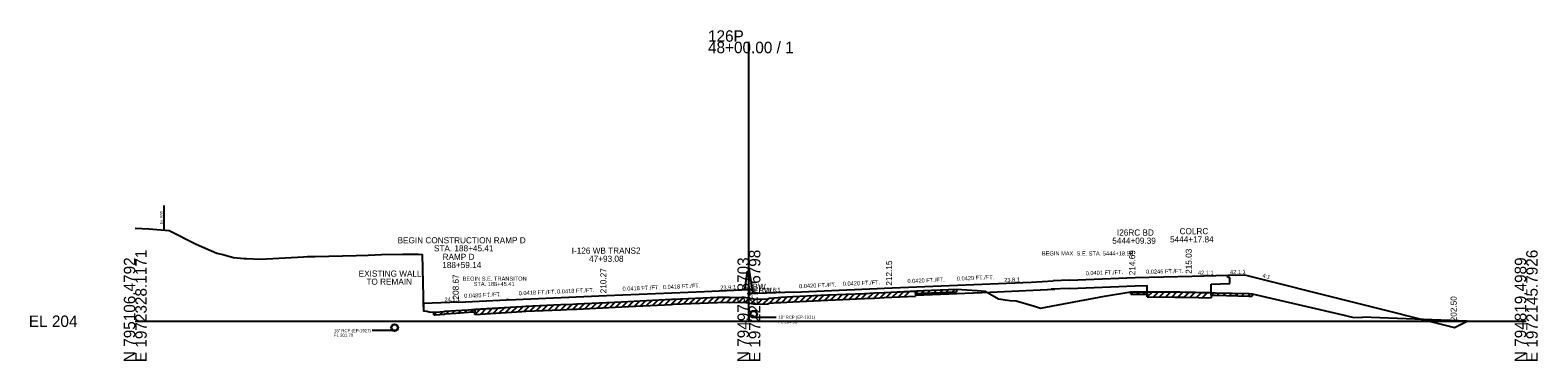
# Model space of a CAD drawing. Extents: x -161 to 1970889, y -4362 to 797231.
# Drawn here: x 1974.3 to 2342.8, y 490.3 to 571.2 of the extents above; entities that cross this region are included whole.
import ezdxf

# ---------------------------------------------------------------- set-up
doc = ezdxf.new("R2010")
doc.units = 0
for name, color, linetype in [('RD_GPK_XS_Cell', 7, 'Continuous'), ('RD_XS_Base', 7, 'Continuous'), ('RD_XS_EarthShd', 7, 'Continuous'), ('RD_XS_ExGround', 7, 'Continuous'), ('RD_XS_ExPaveRet', 7, 'Continuous'), ('RD_XS_ExRW', 7, 'Continuous'), ('RD_XS_MedBWall', 7, 'Continuous'), ('RD_XS_Misc_Line', 7, 'Continuous'), ('RD_XS_Pave', 7, 'Continuous'), ('RD_XS_PaveOvlay', 7, 'Continuous'), ('RD_XS_PaveShd', 7, 'Continuous'), ('RD_XS_Pipe', 7, 'Continuous'), ('RD_XS_TieSlope', 7, 'Continuous'), ('RD_XS_TX_Elev_EX', 7, 'Continuous'), ('RD_XS_TX_Elev_PR', 7, 'Continuous'), ('RD_XS_TX_Misc', 7, 'Continuous'), ('RD_XS_TX_MkPT', 7, 'Continuous'), ('RD_XS_TX_Notes', 7, 'Continuous'), ('RD_XS_TX_Profile', 7, 'Continuous'), ('RD_XS_TX_ShdSlope', 7, 'Continuous'), ('RD_XS_TX_Slope', 7, 'Continuous'), ('RD_XS_TX_Station', 7, 'Continuous')]:
    doc.layers.add(name, color=color, linetype=linetype)

msp = doc.modelspace()

# ---------------------------------------------------------------- linework, layer by layer
at = {"layer": 'RD_GPK_XS_Cell'}
for p, q in [((2150, 500), (2150, 568.35)), ((2000, 500), (2150, 500)), ((2150, 500), (2340, 500))]:
    msp.add_line(p, q, dxfattribs=at)
at = {"layer": 'RD_XS_Base'}
for p, q in [((2228.36, 508.01), (2244.42, 508.65)), ((2244.42, 508.65), (2247.37, 508.72)), ((2262.95, 509.1), (2267.58, 509.21)), ((2267.08, 510.68), (2267.08, 511.24)), ((2267.58, 510.69), (2267.08, 510.68)), ((2267.58, 509.21), (2267.58, 510.69)), ((2190.72, 506.35), (2209, 507.12)), ((2209, 507.12), (2219.5, 507.56)), ((2219.5, 507.56), (2224.75, 507.86)), ((2228.36, 508.01), (2223.84, 507.83)), ((2228.36, 508), (2223.84, 507.82))]:
    msp.add_line(p, q, dxfattribs=at)
at = {"layer": 'RD_XS_EarthShd'}
msp.add_line((2267.08, 511.24), (2271.11, 511.34), dxfattribs=at)
at = {"layer": 'RD_XS_ExGround'}
msp.add_line((2325.53, 500.03), (2300, 501), dxfattribs=at)
msp.add_lwpolyline([(2000, 522.78), (2003.3, 522.58), (2008.25, 522.19), (2014.85, 518.85), (2019.97, 516.66), (2021.39, 516.29), (2024.04, 515.61), (2026.58, 515.36), (2027.11, 515.34), (2030.62, 515.18), (2041.15, 515.78), (2042.08, 515.83), (2043.57, 515.87), (2043.99, 515.87), (2053.97, 516.1), (2056.89, 516.19), (2060.17, 516.3), (2065.43, 516.37), (2069.26, 516.36), (2070.12, 516.35), (2070.44, 502.56), (2071.29, 502.44), (2071.85, 502.33), (2072.88, 502.23), (2073.29, 502.19), (2075.52, 502.35), (2075.69, 502.44), (2078.36, 502.62), (2081.45, 502.82), (2094.53, 503.61), (2095.44, 503.67), (2104, 504.06), (2106.99, 504.2), (2107.92, 504.24), (2118.87, 504.76), (2131.08, 505.38), (2131.48, 505.4), (2142.35, 505.87), (2145.14, 505.88), (2145.34, 505.83), (2148.73, 505.92), (2150.22, 505.64), (2151.52, 505.41), (2154.65, 505.51), (2154.96, 505.67), (2157.16, 505.82), (2157.83, 505.86), (2160.72, 506.01), (2169.28, 506.42), (2178.22, 506.81), (2180.8, 506.92), (2183.07, 507.03), (2192.71, 507.49), (2198.75, 507.76), (2200.72, 507.85), (2205.83, 507.52), (2207.74, 507.38), (2208.89, 506.69), (2211.03, 505.48), (2213.8, 505.08), (2215.34, 504.95), (2219.82, 503.65), (2221.25, 503.17), (2226.88, 504.24), (2236.94, 506.1), (2243.33, 507.21), (2245.08, 507.22), (2247.12, 507.21), (2254.1, 507.17), (2255.31, 507.16), (2256.72, 507.13), (2263.93, 506.98), (2272.3, 506.74), (2273.04, 506.72), (2294.14, 501.81), (2297.84, 500.93), (2300, 501)], dxfattribs=at)
at = {"layer": 'RD_XS_ExPaveRet'}
for p, q in [((2160.72, 504.76), (2169.28, 505.17)), ((2169.28, 505.17), (2178.22, 505.56)), ((2178.22, 505.56), (2180.8, 505.67)), ((2180.8, 505.67), (2183.07, 505.78)), ((2183.07, 505.78), (2190.72, 506.14)), ((2190.72, 507.39), (2190.72, 506.14)), ((2190.72, 506.77), (2190.72, 507.39)), ((2190.72, 506.77), (2192.71, 506.86)), ((2192.71, 506.86), (2198.75, 507.14)), ((2198.75, 507.14), (2200.72, 507.22)), ((2200.72, 507.85), (2200.72, 507.22)), ((2243.33, 506.59), (2243.33, 507.21)), ((2243.33, 506.59), (2245.08, 506.59)), ((2245.08, 506.59), (2247.12, 506.58)), ((2247.12, 506.58), (2247.37, 506.58)), ((2247.37, 505.96), (2247.37, 507.21)), ((2247.37, 507.21), (2247.37, 506.58)), ((2247.37, 505.96), (2254.1, 505.92)), ((2254.1, 505.92), (2255.31, 505.91)), ((2255.31, 505.91), (2256.72, 505.88)), ((2256.72, 505.88), (2262.95, 505.75)), ((2262.95, 507), (2262.95, 505.75)), ((2262.95, 506.38), (2262.95, 507)), ((2262.95, 506.38), (2263.93, 506.36)), ((2263.93, 506.36), (2272.3, 506.11)), ((2272.3, 506.11), (2273.04, 506.09)), ((2273.04, 506.72), (2273.04, 506.09)), ((2072.97, 501.6), (2072.97, 502.23)), ((2072.97, 501.6), (2073.29, 501.57)), ((2073.29, 501.57), (2075.52, 501.73)), ((2075.52, 501.73), (2075.69, 501.81)), ((2075.69, 501.81), (2078.36, 501.99)), ((2078.36, 501.99), (2081.45, 502.19)), ((2081.45, 502.19), (2082.97, 502.28)), ((2082.97, 501.66), (2082.97, 502.91)), ((2082.97, 502.91), (2082.97, 502.28)), ((2082.97, 501.66), (2094.53, 502.36)), ((2094.53, 502.36), (2095.44, 502.42)), ((2095.44, 502.42), (2104, 502.81)), ((2104, 502.81), (2106.99, 502.95)), ((2106.99, 502.95), (2107.92, 502.99)), ((2107.92, 502.99), (2118.87, 503.51)), ((2118.87, 503.51), (2131.08, 504.13)), ((2131.08, 504.13), (2131.48, 504.15)), ((2131.48, 504.15), (2142.35, 504.62)), ((2142.35, 504.62), (2145.14, 504.63)), ((2145.14, 504.63), (2145.34, 504.58)), ((2145.34, 504.58), (2148.73, 504.67)), ((2148.73, 504.67), (2150.22, 504.39)), ((2150.22, 504.39), (2151.52, 504.16)), ((2151.52, 504.16), (2154.65, 504.26)), ((2154.65, 504.26), (2154.96, 504.42)), ((2154.96, 504.42), (2157.16, 504.57)), ((2157.16, 504.57), (2157.83, 504.61)), ((2157.83, 504.61), (2160.72, 504.76))]:
    msp.add_line(p, q, dxfattribs=at)
at = {"layer": 'RD_XS_ExRW'}
msp.add_line((2006.95, 528.29), (2006.95, 522.29), dxfattribs=at)
at = {"layer": 'RD_XS_MedBWall'}
for p, q in [((2149, 507.68), (2149.67, 512.22)), ((2150.18, 512.22), (2149.67, 512.22)), ((2151, 506.72), (2150.18, 512.22))]:
    msp.add_line(p, q, dxfattribs=at)
at = {"layer": 'RD_XS_Misc_Line'}
for p, q in [((2120.5, 503.6), (2121.82, 504.91)), ((2122, 503.67), (2123.32, 504.99)), ((2123.5, 503.75), (2124.82, 505.06)), ((2125, 503.82), (2126.32, 505.14)), ((2126.5, 503.9), (2127.82, 505.22)), ((2128.01, 503.98), (2129.32, 505.29)), ((2129.51, 504.05), (2130.82, 505.37)), ((2131.01, 504.13), (2132.31, 505.43)), ((2132.51, 504.19), (2133.82, 505.5)), ((2134.01, 504.26), (2135.32, 505.56)), ((2135.51, 504.32), (2136.82, 505.63)), ((2137.01, 504.39), (2138.32, 505.69)), ((2138.51, 504.45), (2139.82, 505.76)), ((2140.01, 504.52), (2141.32, 505.82)), ((2141.51, 504.58), (2142.8, 505.87)), ((2143.02, 504.62), (2144.27, 505.87)), ((2144.52, 504.62), (2145.73, 505.84)), ((2146.02, 504.6), (2147.3, 505.88)), ((2147.52, 504.63), (2148.79, 505.91)), ((2149.02, 504.61), (2150.08, 505.67)), ((2150.52, 504.34), (2151.59, 505.41)), ((2152.02, 504.17), (2153.32, 505.47)), ((2153.52, 504.23), (2154.97, 505.67)), ((2155.02, 504.42), (2156.37, 505.77)), ((2156.52, 504.53), (2157.86, 505.86)), ((2158.03, 504.62), (2159.34, 505.94)), ((2159.53, 504.7), (2160.84, 506.01)), ((2161.03, 504.77), (2162.34, 506.09)), ((2162.53, 504.85), (2163.84, 506.16)), ((2164.03, 504.92), (2165.34, 506.23)), ((2165.53, 504.99), (2166.84, 506.3)), ((2167.03, 505.06), (2168.35, 506.38)), ((2168.53, 505.14), (2169.84, 506.45)), ((2170.03, 505.2), (2171.34, 506.51)), ((2171.53, 505.27), (2172.84, 506.58)), ((2173.04, 505.34), (2174.34, 506.64)), ((2174.54, 505.4), (2175.84, 506.71)), ((2176.04, 505.47), (2177.35, 506.77)), ((2177.54, 505.53), (2178.85, 506.84)), ((2179.04, 505.6), (2180.35, 506.9)), ((2180.54, 505.66), (2181.85, 506.97)), ((2182.04, 505.73), (2183.35, 507.04)), ((2183.54, 505.8), (2184.86, 507.11)), ((2185.04, 505.87), (2186.36, 507.19)), ((2186.54, 505.94), (2187.86, 507.26)), ((2188.05, 506.02), (2189.36, 507.33)), ((2190.72, 506.77), (2191.38, 507.43)), ((2192.22, 506.84), (2192.88, 507.5)), ((2193.73, 506.91), (2194.38, 507.56)), ((2195.23, 506.98), (2195.88, 507.63)), ((2196.73, 507.04), (2197.38, 507.7)), ((2198.23, 507.11), (2198.88, 507.77)), ((2199.73, 507.18), (2200.38, 507.83)), ((2243.33, 506.59), (2243.96, 507.21)), ((2244.83, 506.59), (2245.45, 507.22)), ((2246.33, 506.59), (2246.95, 507.21)), ((2247.37, 505.96), (2248.61, 507.2)), ((2248.87, 505.95), (2250.11, 507.19)), ((2250.37, 505.94), (2251.61, 507.18)), ((2251.87, 505.93), (2253.12, 507.18)), ((2253.37, 505.92), (2254.61, 507.17)), ((2254.87, 505.91), (2256.1, 507.14)), ((2256.37, 505.89), (2257.6, 507.11)), ((2257.87, 505.86), (2259.1, 507.08)), ((2259.38, 505.83), (2260.6, 507.05)), ((2260.88, 505.8), (2262.1, 507.02)), ((2262.95, 506.38), (2263.56, 506.99)), ((2264.45, 506.34), (2265.06, 506.95)), ((2265.95, 506.3), (2266.56, 506.91)), ((2267.45, 506.26), (2268.06, 506.86)), ((2268.95, 506.21), (2269.56, 506.82)), ((2270.45, 506.17), (2271.06, 506.77)), ((2271.96, 506.12), (2272.56, 506.73)), ((2072.97, 501.6), (2073.58, 502.21)), ((2074.47, 501.65), (2075.14, 502.32)), ((2075.97, 501.83), (2076.64, 502.5)), ((2077.47, 501.93), (2078.14, 502.6)), ((2078.97, 502.03), (2079.64, 502.7)), ((2080.47, 502.13), (2081.14, 502.8)), ((2081.97, 502.22), (2082.64, 502.89)), ((2082.97, 501.66), (2084.31, 502.99)), ((2084.48, 501.75), (2085.81, 503.08)), ((2085.98, 501.84), (2087.31, 503.17)), ((2087.48, 501.93), (2088.81, 503.27)), ((2088.98, 502.03), (2090.31, 503.36)), ((2090.48, 502.12), (2091.81, 503.45)), ((2091.98, 502.21), (2093.31, 503.54)), ((2093.48, 502.3), (2094.81, 503.63)), ((2094.98, 502.39), (2096.3, 503.71)), ((2096.48, 502.47), (2097.79, 503.78)), ((2097.98, 502.53), (2099.3, 503.84)), ((2099.49, 502.6), (2100.8, 503.91)), ((2100.99, 502.67), (2102.3, 503.98)), ((2102.49, 502.74), (2103.8, 504.05)), ((2103.99, 502.81), (2105.3, 504.12)), ((2105.49, 502.88), (2106.8, 504.19)), ((2106.99, 502.95), (2108.3, 504.26)), ((2108.49, 503.02), (2109.81, 504.33)), ((2109.99, 503.09), (2111.31, 504.4)), ((2111.49, 503.16), (2112.81, 504.48)), ((2113, 503.23), (2114.31, 504.55)), ((2114.5, 503.31), (2115.81, 504.62)), ((2116, 503.38), (2117.31, 504.69)), ((2117.5, 503.45), (2118.81, 504.76)), ((2119, 503.52), (2120.32, 504.84))]:
    msp.add_line(p, q, dxfattribs=at)
at = {"layer": 'RD_XS_Pave'}
for p, q in [((2185, 508.15), (2209, 509.16)), ((2228.36, 510.05), (2244.42, 510.69)), ((2244.42, 510.69), (2258.24, 511.03)), ((2079.09, 504.66), (2090.73, 505.23)), ((2091.17, 505.26), (2115.17, 506.27)), ((2115.17, 506.27), (2139.17, 507.27)), ((2161, 507.14), (2185, 508.15))]:
    msp.add_line(p, q, dxfattribs=at)
at = {"layer": 'RD_XS_PaveOvlay'}
for p, q in [((2247.37, 507.21), (2247.37, 508.72)), ((2262.95, 507), (2262.95, 509.1)), ((2118.87, 504.76), (2131.08, 505.38)), ((2131.08, 505.38), (2131.48, 505.4)), ((2131.48, 505.4), (2142.35, 505.87)), ((2142.35, 505.87), (2145.14, 505.88)), ((2145.14, 505.88), (2145.34, 505.83)), ((2145.34, 505.83), (2148.73, 505.92)), ((2148.73, 505.92), (2150.22, 505.64)), ((2150.22, 505.64), (2151.52, 505.41)), ((2151.52, 505.41), (2154.65, 505.51)), ((2154.65, 505.51), (2154.96, 505.67)), ((2154.96, 505.67), (2157.16, 505.82)), ((2157.16, 505.82), (2157.83, 505.86)), ((2157.83, 505.86), (2160.72, 506.01)), ((2160.72, 506.01), (2169.28, 506.42)), ((2169.28, 506.42), (2178.22, 506.81)), ((2178.22, 506.81), (2180.8, 506.92)), ((2180.8, 506.92), (2183.07, 507.03)), ((2183.07, 507.03), (2190.72, 507.39)), ((2190.72, 507.39), (2190.72, 506.35)), ((2247.37, 507.21), (2255.31, 507.16)), ((2255.31, 507.16), (2262.95, 507)), ((2082.97, 502.91), (2094.53, 503.61)), ((2094.53, 503.61), (2095.44, 503.67)), ((2095.44, 503.67), (2104, 504.06)), ((2104, 504.06), (2106.99, 504.2)), ((2106.99, 504.2), (2107.92, 504.24)), ((2107.92, 504.24), (2118.87, 504.76))]:
    msp.add_line(p, q, dxfattribs=at)
msp.add_lwpolyline([(2070.4, 504.3), (2070.44, 502.56), (2071.29, 502.44), (2071.85, 502.33), (2072.88, 502.23), (2073.29, 502.19), (2075.52, 502.35), (2075.69, 502.44), (2078.36, 502.62), (2081.45, 502.82), (2082.97, 502.91)], dxfattribs=at)
at = {"layer": 'RD_XS_PaveShd'}
for p, q in [((2209, 509.16), (2219, 509.58)), ((2219, 509.58), (2224.34, 509.89)), ((2228.36, 510.05), (2224.34, 509.89)), ((2258.24, 511.03), (2267.08, 511.24)), ((2091.17, 505.26), (2090.73, 505.23)), ((2139.17, 507.27), (2150, 507.72)), ((2150, 506.68), (2150, 507.72)), ((2161, 507.14), (2150, 506.68)), ((2079.09, 504.66), (2070.4, 504.3))]:
    msp.add_line(p, q, dxfattribs=at)
at = {"layer": 'RD_XS_Pipe'}
for p, q in [((2062.88, 497.7), (2057.88, 497.7)), ((2151.68, 500.98), (2156.68, 500.98))]:
    msp.add_line(p, q, dxfattribs=at)
for centre, radius in [((2151.18, 501.73), 0.85), ((2151.18, 501.73), 0.75), ((2063.38, 498.45), 0.85), ((2063.38, 498.45), 0.75)]:
    msp.add_circle(centre, radius, dxfattribs=at)
at = {"layer": 'RD_XS_TieSlope'}
for p, q in [((2271.11, 511.34), (2322.46, 498.5)), ((2322.46, 498.5), (2325.53, 500.03))]:
    msp.add_line(p, q, dxfattribs=at)

# ---------------------------------------------------------------- texts
at = {"layer": 'RD_GPK_XS_Cell'}
for s, p in [('48+00.00 / 1', (2140, 565.55)), ('126P', (2140, 568.35)), ('EL 204', (1974, 498.6))]:
    msp.add_text(s, height=2.8, dxfattribs=at).set_placement(p)
for s, p in [('E 1972328.1171', (2002.8, 490)), ('E 1972247.6798', (2152.8, 490)), ('E 1972145.7926', (2342.8, 490)), ('N 795106.4792', (2000, 490)), ('N 794979.8703', (2150, 490)), ('N 794819.4989', (2340, 490))]:
    msp.add_text(s, height=2.8, rotation=90, dxfattribs=at).set_placement(p)
at = {"layer": 'RD_XS_ExRW'}
msp.add_text('Ex. R/W ', height=0.65, rotation=90, dxfattribs=at).set_placement((2006.7, 523.68))
at = {"layer": 'RD_XS_Pipe'}
for s, p in [('18" RCP (EP-1931)', (2157.18, 500.61)), ('18" RCP (EP-1927)', (2048.58, 497.32)), ('FL 204.98', (2157.18, 499.48)), ('FL 201.70', (2048.58, 496.2))]:
    msp.add_text(s, height=0.75, dxfattribs=at).set_placement(p)
at = {"layer": 'RD_XS_TX_Elev_EX'}
msp.add_text('209.69', height=1, rotation=90, dxfattribs=at).set_placement((2151, 505.69))
at = {"layer": 'RD_XS_TX_Elev_PR'}
for s, p in [(' 214.69', (2244.42, 510.69)), (' 215.03', (2258.24, 511.03)), (' 210.27', (2115.17, 506.27)), (' 212.15', (2185, 508.15)), (' 208.67', (2079.09, 504.75))]:
    msp.add_text(s, height=1.5, rotation=90, dxfattribs=at).set_placement(p)
at = {"layer": 'RD_XS_TX_Misc'}
msp.add_text('202.50', height=1.5, rotation=90, dxfattribs=at).set_placement((2323.01, 499.98))
at = {"layer": 'RD_XS_TX_MkPT'}
for s, p in [('WBW', (2149, 507.68)), ('EBW', (2151, 506.72))]:
    msp.add_text(s, height=1.5, dxfattribs=at).set_placement(p)
at = {"layer": 'RD_XS_TX_Notes'}
for s, height, p in [('BEGIN CONSTRUCTION RAMP D', 1.5, (2064.12, 519.05)), ('STA. 188+45.41', 1.5, (2073, 517.09)), ('BEGIN MAX. S.E. STA. 5444+18.58', 1, (2221.62, 516.08)), ('EXISTING WALL', 1.5, (2054.61, 510.9)), ('TO REMAIN', 1.5, (2056.5, 508.93)), ('BEGIN S.E. TRANSITON', 1, (2080.02, 509.91)), ('STA. 188+45.41', 1, (2082.71, 508.6))]:
    msp.add_text(s, height=height, dxfattribs=at).set_placement(p)
at = {"layer": 'RD_XS_TX_Profile'}
for s, rotation, p in [('23.9:1', 2.3955, (2143, 507.68)), ('23.8:1', 2.405, (2212.41, 509.55)), ('23.8:1', 2.405, (2153.91, 507.09))]:
    msp.add_text(s, height=1, rotation=rotation, dxfattribs=at).set_placement(p)
at = {"layer": 'RD_XS_TX_ShdSlope'}
msp.add_text('42.1:1', height=1, rotation=1.3602, dxfattribs=at).set_placement((2267.61, 511.51))
at = {"layer": 'RD_XS_TX_Slope'}
for s, rotation, p in [('0.0401 FT./FT.', 2.2975, (2232.33, 511.21)), ('0.0246 FT./FT.', 1.4067, (2247.09, 511.6)), ('42.1:1', 1.3602, (2259.77, 511.32)), ('0.0418 FT./FT.', 2.3955, (2119.13, 507.43)), ('0.0418 FT./FT.', 2.3955, (2128.99, 507.84)), ('0.0420 FT./FT.', 2.405, (2162.28, 508.07)), ('0.0420 FT./FT.', 2.405, (2172.96, 508.65)), ('0.0420 FT./FT.', 2.405, (2188.77, 509.31)), ('0.0420 FT./FT.', 2.405, (2200.85, 509.91)), ('4:1', 344.1175, (2275.44, 510.79)), ('24.1:1', 2.3803, (2075.6, 504.77)), ('0.0485 FT./FT.', 2.3955, (2080.42, 505.7)), ('0.0418 FT./FT.', 2.3955, (2093.75, 506.34)), ('0.0418 FT./FT.', 2.3955, (2103.13, 506.76))]:
    msp.add_text(s, height=1, rotation=rotation, dxfattribs=at).set_placement(p)
at = {"layer": 'RD_XS_TX_Station'}
for s, p in [('5444+09.39', (2238.81, 518.94)), ('I26RC BD', (2239.96, 520.94)), ('5444+17.84', (2252.94, 519.28)), ('COLRC', (2255.27, 521.28)), ('RAMP D', (2075.12, 515)), ('I-126 WB TRANS2', (2106.68, 516.52)), ('47+93.08', (2110.93, 514.52)), ('188+59.14', (2075.04, 513))]:
    msp.add_text(s, height=1.5, dxfattribs=at).set_placement(p)

doc.saveas('drawing.dxf')
